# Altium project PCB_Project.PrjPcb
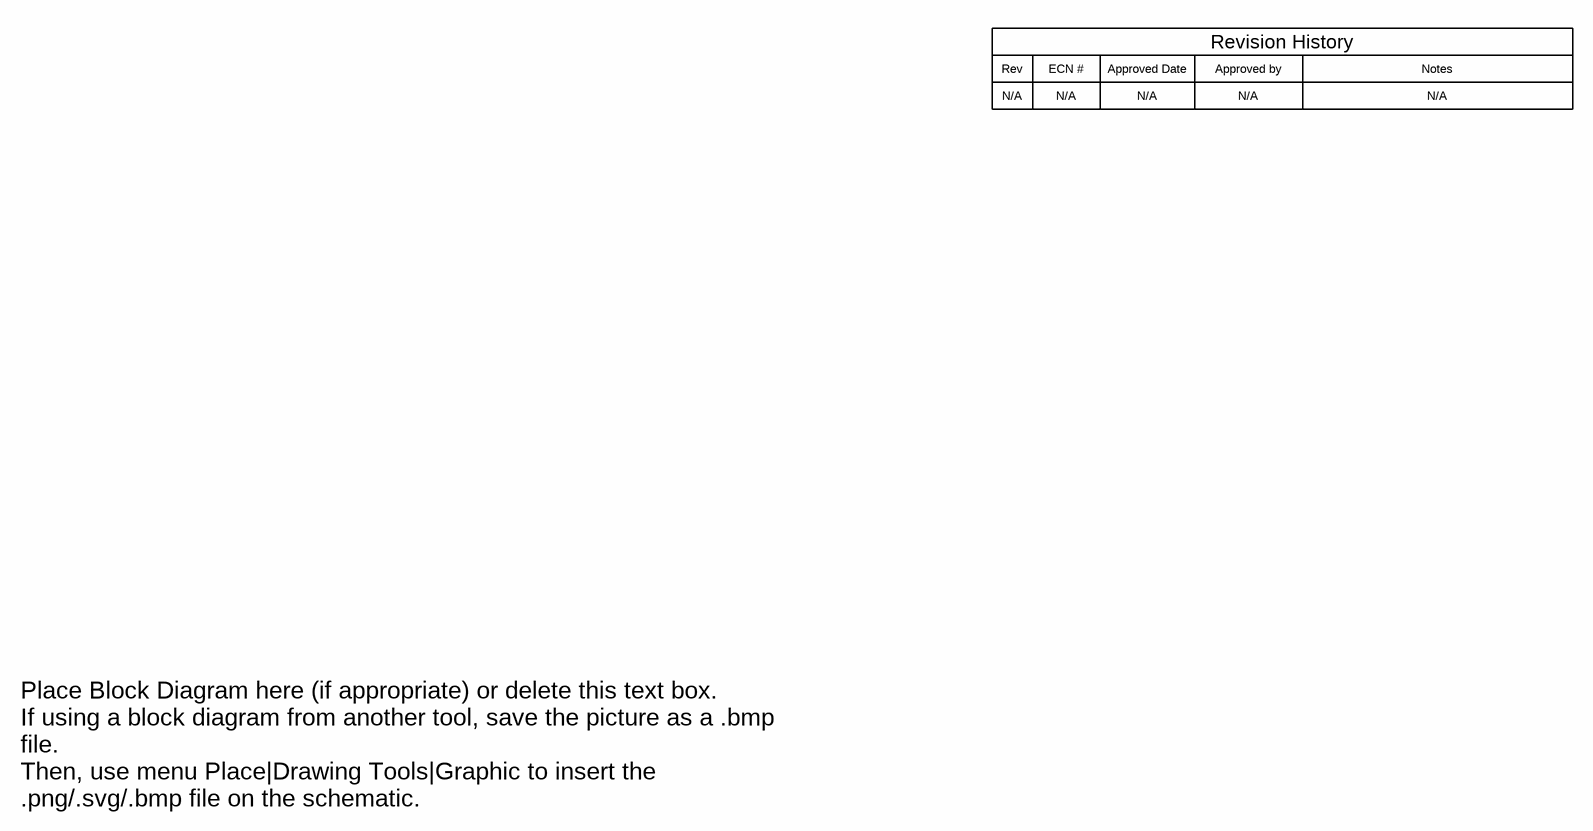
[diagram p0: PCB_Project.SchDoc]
TID: N/A; TechSupport: http://www.ti.com/support; SCH_Rev: E1; PRJ_Title: One Phage E-meteing with M0C; PRJ_Number: N/A; PRJ_Engineer: Joe Wang; PRJ_Customer: Public Release; PCB_Rev: E1; PCB_Layout: Joe Wang; CopyrightYear: 2025
3 sheets, 67 parts. Net scope: global (net labels, ports and power ports of the same name join across sheets).
Board file: PCB_Project.PcbDoc
Sheets:
  PCB_Project.SchDoc
  PCB_Project_BlankSheet.SchDoc
  PCB_Project_Hardware.SchDoc

## Sheet PCB_Project.SchDoc
size 431 x 279 mm; Date: Not shown in title block; ApprovedBy: Not shown in title block; CheckedBy: Not shown in title block; Author: Not shown in title block; CompanyName: Not shown in title block; Engineer: Not shown in title block; Organization: Not shown in title block; Address1: Not shown in title block; Address2: Not shown in title block; Address3: Not shown in title block; Address4: Not shown in title block; DocumentNumber: 1; Revision: Use project parameter SCH_Rev; SheetNumber: 1; SheetTotal: 3; PageSetup: Record=PageOptions¦CenterHorizontal=True¦CenterVertical=True¦PrintScale=1.00¦XCorrection=1.00¦YCorrection=1.00¦PrintKind=0¦BorderSize=5000000¦LeftOffset=0¦BottomOffset=0¦Orientation=2¦PaperLength=1000¦PaperWidth=1000¦Scale=100¦PaperSource=15¦PrintQuality=600¦MediaType=1¦DitherType=10¦PaperKind=Letter¦PrintScaleMode=1

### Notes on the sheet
- Rev
- N/A
- ECN #
- Approved Date
- Approved by
- Revision History
- Notes
- Place Block Diagram here (if appropriate) or delete this text box.
  If using a block diagram from another tool, save the picture as a .bmp file.
  Then, use menu Place|Drawing Tools|Graphic to insert the .png/.svg/.bmp file on the schematic.

## Sheet PCB_Project_BlankSheet.SchDoc
size 431 x 279 mm; Date: Not shown in title block; ApprovedBy: Not shown in title block; CheckedBy: Not shown in title block; Author: Not shown in title block; CompanyName: Not shown in title block; Engineer: Not shown in title block; Organization: Not shown in title block; Address1: Not shown in title block; Address2: Not shown in title block; Address3: Not shown in title block; Address4: Not shown in title block; DocumentNumber: 2; Revision: Use project parameter SCH_Rev; SheetNumber: 2; SheetTotal: 3; PageSetup: Record=PageOptions¦CenterHorizontal=True¦CenterVertical=True¦PrintScale=1.00¦XCorrection=1.00¦YCorrection=1.00¦PrintKind=0¦BorderSize=5000000¦LeftOffset=0¦BottomOffset=0¦Orientation=2¦PaperLength=1000¦PaperWidth=1000¦Scale=100¦PaperSource=15¦PrintQuality=600¦MediaType=1¦DitherType=10¦PaperKind=Letter¦PrintScaleMode=1
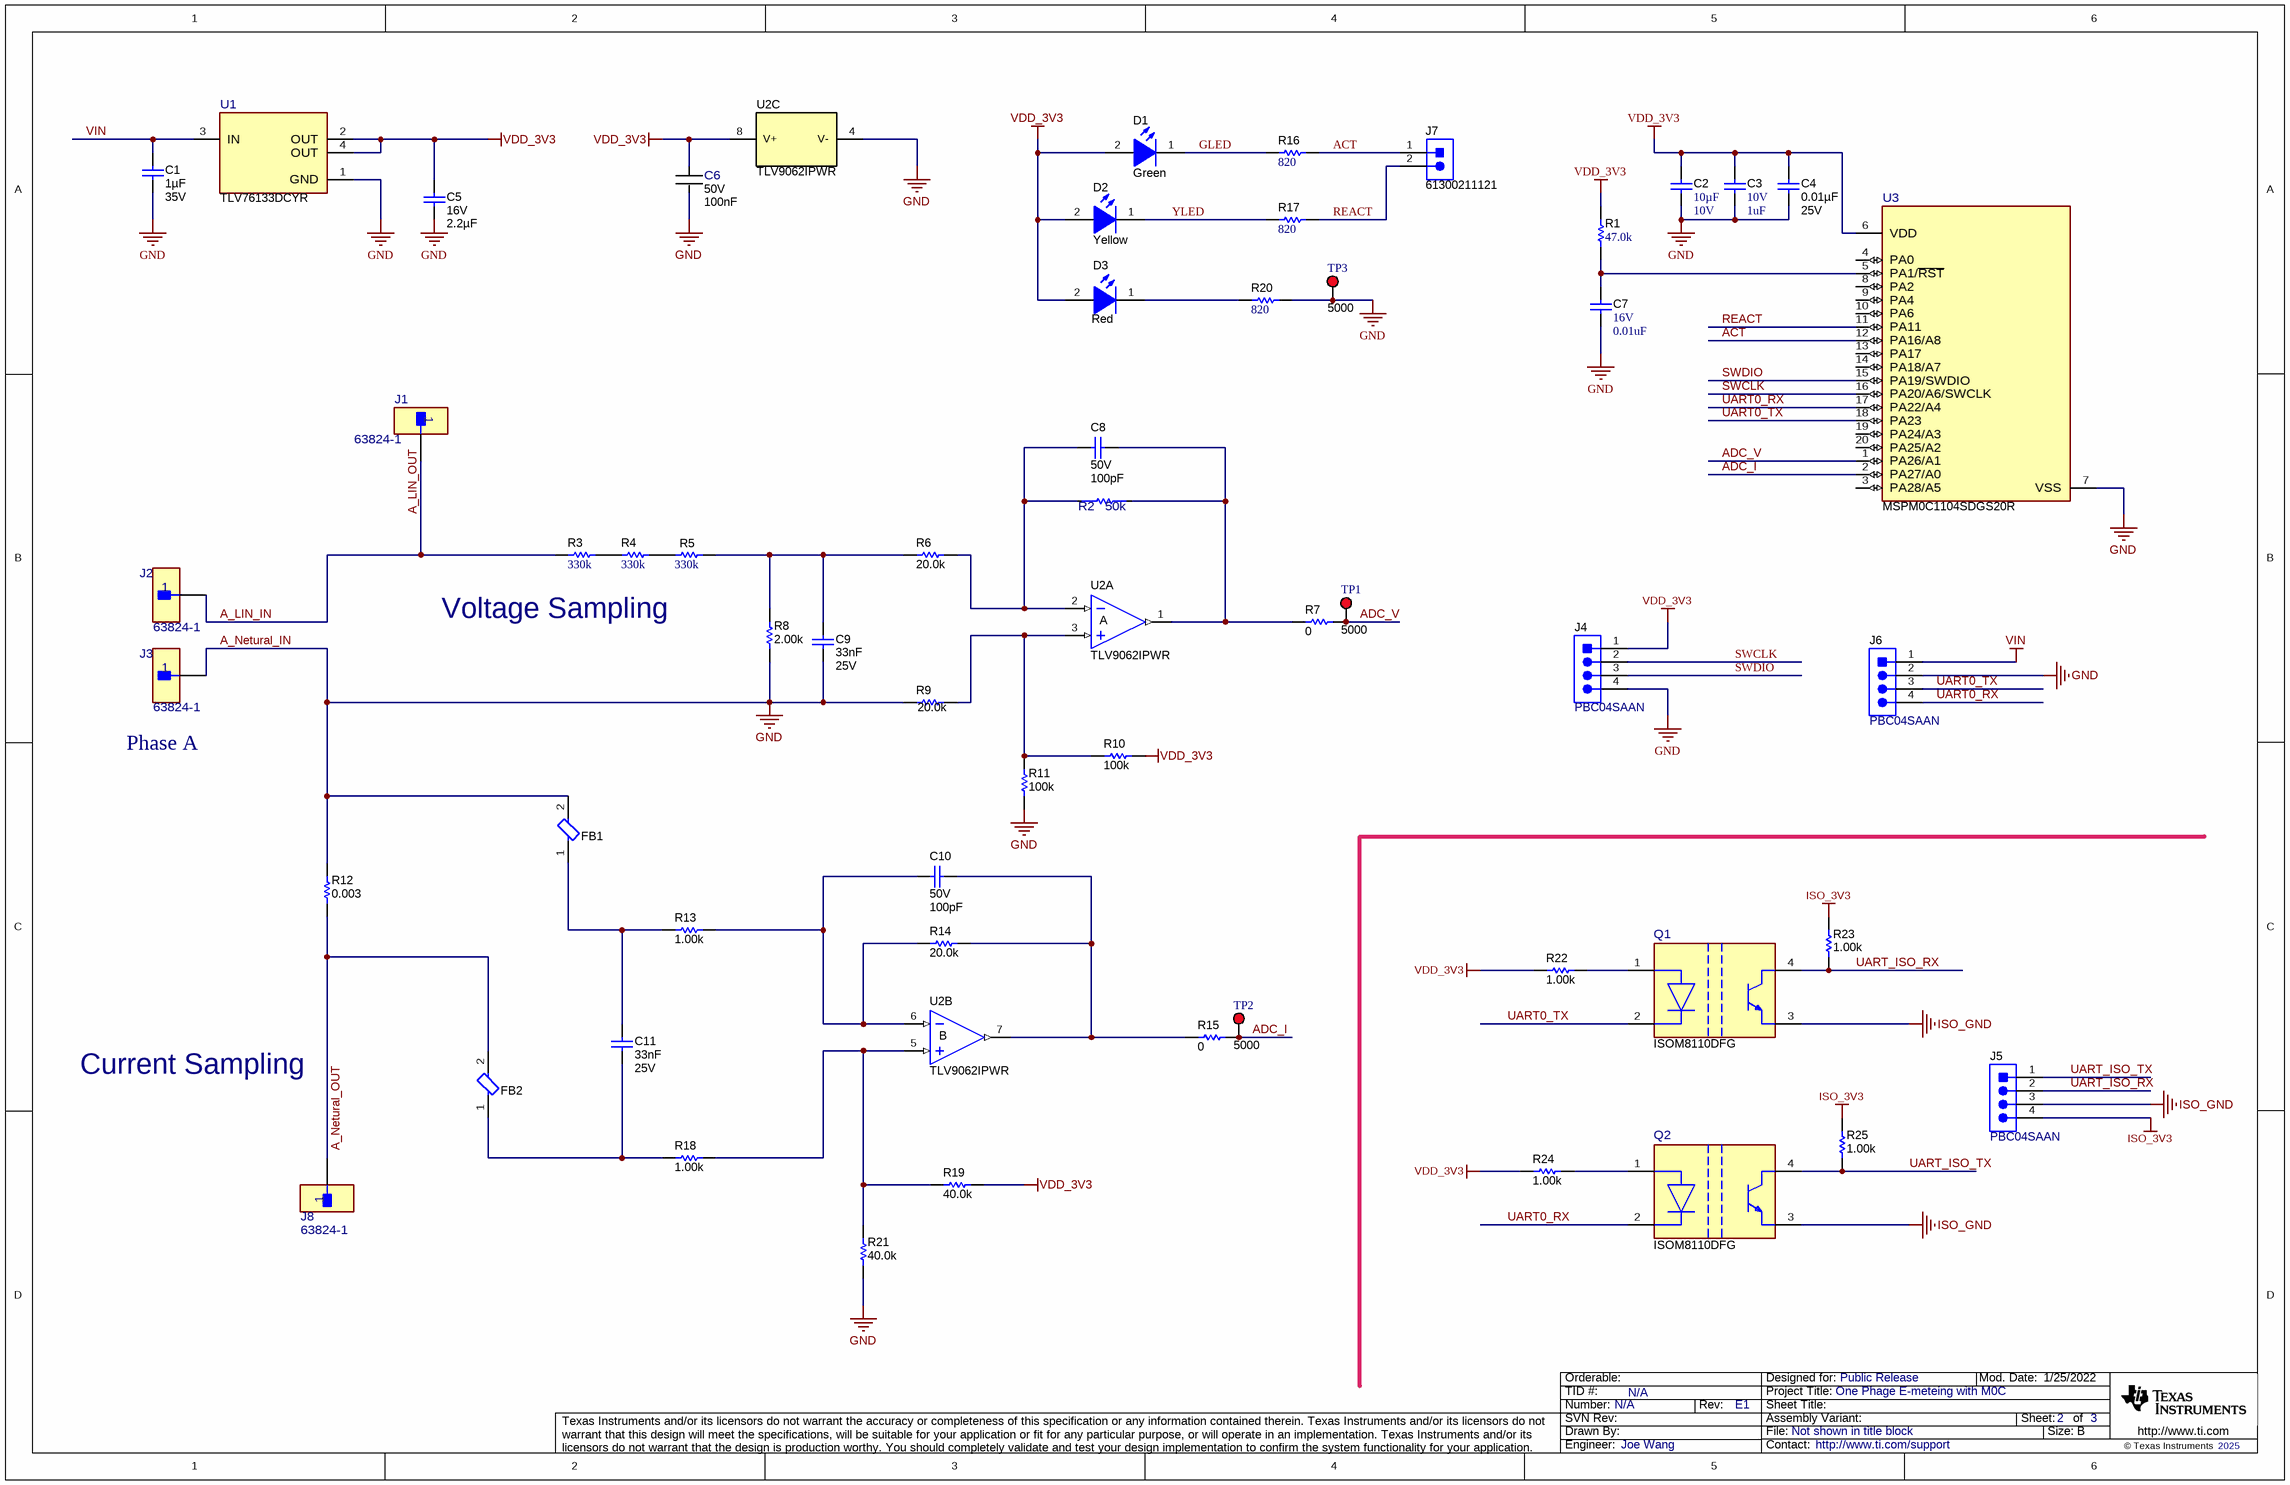
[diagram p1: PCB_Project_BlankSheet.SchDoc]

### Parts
C1  Cap_F: 1µF  VDC_V: 35V  [0603]  (hidden comment: CGA3E1X7R1V105K080AE)
C2  ValueDisplayed: 10µF  VDC_V: 10V  [0603]  (hidden comment: GRM188R61A106KAALD)
C3  VDC_V: 10V  ValueDisplayed: 1uF  [0402]  (hidden comment: GRM155C81A105KA12D)
C4  ValueDisplayed: 0.01µF  VDC_V: 25V  [0402]  (hidden comment: 04023C103JAT2A)
C5  VDC_V: 16V  Cap_F: 2.2µF  [0603]  (hidden comment: GRM188Z71C225KE43)
C6  VDC_V: 50V  Cap_F: 100nF  [FP-CL10B104KB8NNNC_0603-IPC_B]  (hidden comment: CL10B104KB8NNNC)
C7  VDC_V: 16V  ValueDisplayed: 0.01uF  [0402]  (hidden comment: C1005X7R1C103K050BA)
C8  VDC_V: 50V  ValueDisplayed: 100pF  [0603]  (hidden comment: C0603C101F5GACTU)
C9  Cap_F: 33nF  VDC_V: 25V  [0603]  (hidden comment: C0603C333J3RACTU)
C10  VDC_V: 50V  ValueDisplayed: 100pF  [0603]  (hidden comment: C0603C101F5GACTU)
C11  Cap_F: 33nF  VDC_V: 25V  [0603]  (hidden comment: C0603C333J3RACTU)
D1  value Green  [WL-SMCW_GREEN]  (hidden comment: 150060VS75000)
D2  value Yellow  [WL-SMCW_YELLOW]  (hidden comment: 150060YS75000)
D3  value Red  [WL-SMCW_RED]  (hidden comment: 150060RS75000)
FB1  74269244182  [FP-74269244182_0402-MFG]  (value not drawn)
FB2  74269244182  [FP-74269244182_0402-MFG]  (value not drawn)
J1  63824-1  [FP-63824-1_CONN_7MM92_3MM11-MFG]
J2  63824-1  [FP-63824-1_CONN_7MM92_3MM11-MFG]
J3  63824-1  [FP-63824-1_CONN_7MM92_3MM11-MFG]
J4  PBC04SAAN  [Sullins_xxC04SAAN]
J5  PBC04SAAN  [Sullins_xxC04SAAN]
J6  PBC04SAAN  [Sullins_xxC04SAAN]
J7  61300211121  [WURTH_61300211121]
J8  63824-1  [FP-63824-1_CONN_7MM92_3MM11-MFG]
Q1  ISOM8110DFG  [DFG0004A-MFG]
Q2  ISOM8110DFG  [DFG0004A-MFG]
R1  ValueDisplayed: 47.0k  [0402]  (hidden comment: RC0402FR-0747KL)
R2  50k  [FP-RT0603BRD0750KL_0603-MFG]
R3  ValueDisplayed: 330k  [TNPV1206]  (hidden comment: TNPV1206330KBEEN)
R4  ValueDisplayed: 330k  [TNPV1206]  (hidden comment: TNPV1206330KBEEN)
R5  ValueDisplayed: 330k  [TNPV1206]  (hidden comment: TNPV1206330KBEEN)
R6  ValueDisplayed: 20.0k  [0603]  (hidden comment: RT0603BRD0720KL)
R7  ValueDisplayed: 0  [0603]  (hidden comment: ERJ-3GEY0R00V)
R8  ValueDisplayed: 2.00k  [0603]  (hidden comment: RT0603BRD072KL)
R9  ValueDisplayed: 20.0k  [0603]  (hidden comment: RT0603BRD0720KL)
R10  ValueDisplayed: 100k  [0603]  (hidden comment: RG1608P-104-B-T5)
R11  ValueDisplayed: 100k  [0603]  (hidden comment: RG1608P-104-B-T5)
R12  ValueDisplayed: 0.003  [CRE2512-R1_R4]  (hidden comment: CRE2512-FZ-R003E-3)
R13  ValueDisplayed: 1.00k  [0603]  (hidden comment: RT0603DRE071KL)
R14  ValueDisplayed: 20.0k  [0603]  (hidden comment: RT0603BRD0720KL)
R15  ValueDisplayed: 0  [0603]  (hidden comment: ERJ-3GEY0R00V)
R16  value 820  [0402]  (hidden comment: RC0402FR-07820RL)
R17  value 820  [0402]  (hidden comment: RC0402FR-07820RL)
R18  ValueDisplayed: 1.00k  [0603]  (hidden comment: RT0603DRE071KL)
R19  ValueDisplayed: 40.0k  [0603]  (hidden comment: PAT0603E4002BST1)
R20  value 820  [0402]  (hidden comment: RC0402FR-07820RL)
R21  ValueDisplayed: 40.0k  [0603]  (hidden comment: PAT0603E4002BST1)
R22  ValueDisplayed: 1.00k  [0603]  (hidden comment: RT0603DRE071KL)
R23  ValueDisplayed: 1.00k  [0603]  (hidden comment: RT0603DRE071KL)
R24  ValueDisplayed: 1.00k  [0603]  (hidden comment: RT0603DRE071KL)
R25  ValueDisplayed: 1.00k  [0603]  (hidden comment: RT0603DRE071KL)
TP1  5000  [Keystone5000]
TP2  5000  [Keystone5000]
TP3  5000  [Keystone5000]
U1  TLV76133DCYR  [DCY0004A-MFG]
U2  TLV9062IPWR  [PW0008A_N]  (parts A,B,C of 3)
U3  MSPM0C1104SDGS20R  [DGS0020A-MFG]

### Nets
A_Netural_IN: C1.2 C2.2 C3.2 C4.1 C5.2 C6.2 C7.2 C9.2 FB1.2 J3.1 J4.4 J6.2 R8.1 R9.1 R11.1 R12.2 R20.1 R21.1 TP3.1 U1.1(GND) U2.4(V-) U3.7(VSS)  [also labelled GND]
ISO_3V3: J5.4 R23.2 R25.2
ISO_GND: J5.3 Q1.3(Emitter) Q2.3(Emitter)
VDD_3V3: C2.1 C3.1 C4.2 C5.1 C6.1 D1.2(A) D2.2(A) D3.2(A) J4.1 R1.2 R10.2 R19.1 R22.1 R24.1 U1.2(OUT) U1.4(OUT) U2.8(V+) U3.6(VDD)
VIN: C1.1 J6.1 U1.3(IN)
A_LIN_IN: J1.1 J2.1 R3.2  [also labelled A_LIN_OUT]
A_Netural_OUT: FB2.2 J8.1 R12.1
ACT: J7.1 R16.1 U3.12(PA16/A8)
ADC_I: R15.2 TP2.1 U3.2(PA27/A0)
ADC_V: R7.2 TP1.1 U3.1(PA26/A1)
GLED: D1.1(K) R16.2
REACT: J7.2 R17.1 U3.11(PA11)
SWCLK: J4.2 U3.16(PA20/A6/SWCLK)
SWDIO: J4.3 U3.15(PA19/SWDIO)
UART0_RX: J6.4 Q2.2(CAT) U3.17(PA22/A4)
UART0_TX: J6.3 Q1.2(CAT) U3.18(PA23)
UART_ISO_RX: J5.2 Q1.4(Collector) R23.1
UART_ISO_TX: J5.1 Q2.4(Collector) R25.1
YLED: D2.1(K) R17.2
NetC7_1: C7.1 R1.1 U3.5(PA1/~{RST})
NetC8_1: C8.1 R2.2 R7.1 U2.1(OUT)
NetC8_2: C8.2 R2.1 R6.2 U2.2(IN-)
NetC9_1: C9.1 R5.2 R6.1 R8.2
NetC10_1: C10.1 R14.2 R15.1 U2.7(OUT)
NetC10_2: C10.2 R13.2 R14.1 U2.6(IN-)
NetC11_1: C11.1 FB1.1 R13.1
NetC11_2: C11.2 FB2.1 R18.1
NetD3_1: D3.1(K) R20.2
NetQ1_1: Q1.1(AN) R22.2
NetQ2_1: Q2.1(AN) R24.2
NetR3_1: R3.1 R4.2
NetR4_1: R4.1 R5.1
NetR9_2: R9.2 R10.1 R11.2 U2.3(IN+)
NetR18_2: R18.2 R19.2 R21.2 U2.5(IN+)

Not connected (* = marked no-connect by the designer): U3 3(PA28/A5) 4(PA0) 8(PA2) 9(PA4) 10(PA6) 13(PA17) 14(PA18/A7) 19(PA24/A3) 20(PA25/A2)

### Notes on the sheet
- Voltage Sampling
- Phase A
- Current Sampling

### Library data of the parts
C1 = CMP-0081259-1: CAP, CERM, 1 µF, 35 V,+/- 10%, X7R, AEC-Q200 Grade 1, 0603; Manufacturer: TDK; SizeAreaWB_mm2: 4.68; SizeArea_mm2: 1.28; AEC Qualified: Y; AEC Category: Q200; Value: 1uF; TaMax_C: 125°C; SizeZ_mm: 1; Polarized: N; TaMin_C: -55°C; SizeY_mm: 0.8; U/M: EA; SizeX_mm: 1.6
C2 = CMP-0086193-1: CAP, CERM, 10 µF, 10 V,+/- 10%, X5R, 0603; Manufacturer: MuRata; SizeArea_mm2: 1.28; SizeY_mm: 0.8; TaMax_C: 85°C; TaMin_C: -55°C; Polarized: N; SizeAreaWB_mm2: 4.68; SizeZ_mm: 1; SizeX_mm: 1.6; AEC Category: Q200; U/M: EA; Value: 10uF
C3 = CMP-0064971-2: CAP, CERM, 1 uF, 10 V,+/- 10%, X6S, 0402; Manufacturer: MuRata; TaMin_C: -55°C; Polarized: N; SizeAreaWB_mm2: 3; Value1: Unknown; U/M: EA; Value: 1uF; TaMax_C: 105°C; SizeZ_mm: 0.6; SizeX_mm: 1; SizeY_mm: 0.5; Cap_F: 1µF; AEC Category: Q200
C4 = CMP-0085568-1: CAP, CERM, 0.01 µF, 25 V,+/- 5%, X7R, 0402; Manufacturer: AVX; AEC Category: Q200; SizeAreaWB_mm2: 3; SizeArea_mm2: 0.5; Polarized: N; TaMin_C: -55°C; Value: 0.01uF; U/M: EA; SizeX_mm: 1; Cap_F: 10nF; SizeZ_mm: 0.6; TaMax_C: 125°C
C5 = CMP-0007499-1: CAP, CERM, 2.2 uF, 16 V, +/- 10%, X7R, 0603; Manufacturer: MuRata; TaMin_C: -55°C; Polarized: N; SizeAreaWB_mm2: 4.68; Value1: Unknown; U/M: EA; Value: 2.2uF; TaMax_C: 125°C; SizeZ_mm: 1; SizeX_mm: 1.6; SizeY_mm: 0.8; SizeArea_mm2: 1.28; AEC Category: Q200
C6 = CMP-0087079-1: CAP CER 0.1UF 50V X7R 0603; Manufacturer: Samsung; Tolerance_%: 10%; Symbol Name: SYM-CL10B104KB8NNNC; AEC Qualified: No; TempCo: 15%; SizeZ_mm: 0.9mm
C7 = CMP-0006292-2: CAP, CERM, 0.01 uF, 16 V, +/- 10%, X7R, 0402; Manufacturer: TDK; TaMin_C: -55°C; Polarized: N; SizeAreaWB_mm2: 3; Value1: 0.0623 ohm; U/M: EA; Value: 0.01uF; TaMax_C: 125°C; SizeZ_mm: 0.6; SizeX_mm: 1; SizeY_mm: 0.5; Cap_F: 10nF; AEC Category: Q200; ESR_ohm: 62.3m
C8 C10 = CMP-0080091-1: CAP, CERM, 100 pF, 50 V,+/- 1%, C0G/NP0, 0603; Manufacturer: Kemet; SizeAreaWB_mm2: 4.68; SizeArea_mm2: 1.28; AEC Qualified: N; AEC Category: Q200; Value: 100pF; TaMax_C: 125°C; SizeZ_mm: 1; Green_REACh: Passed; TaMin_C: -55°C; SizeY_mm: 0.8; Green_Lifecycle: Active; U/M: EA; SizeX_mm: 1.6
C9 C11 = CMP-0006923-4: CAP, CERM, 0.033 uF, 25 V, +/- 5%, X7R, 0603; Manufacturer: Kemet; TaMin_C: -55°C; Polarized: N; SizeAreaWB_mm2: 4.68; Value1: Unknown; U/M: EA; TaMax_C: 125°C; SizeZ_mm: 1; SizeX_mm: 1.6; SizeY_mm: 0.8; SizeArea_mm2: 1.28; AEC Category: Q200
D1 = CMP-0002894-2: LED, Green, SMD; Manufacturer: Wurth Elektronik; Type: AlInGaP; Vf_V: 2V; Io_A: 20mA; Value1: W
D2 = CMP-0002892-3: LED, Yellow, SMD; Manufacturer: Wurth Elektronik; Type: AlInGaP; Vf_V: 2V; Io_A: 20mA; Value1: W
D3 = CMP-0002947-2: LED, Red, SMD; Manufacturer: Wurth Elektronik; Io_A: 30mA; Power_TotalModule: 72mW; Vr_V: 5V; Tjmax_C: 85°C; Value1: 0.072W; U/M: EA; Angle: 140; Vf_V: 2V; Type: AlInGaP
FB1 FB2 = CMP-0091663-1: 1.8 kOhms @ 100MHz 1 Power, Signal Line Ferrite Bead 0402 (1005 Metric) 210mA 2.1Ohm; Manufacturer: Wurth Electronics; SizeZ_mm: 0.55mm; AEC Qualified: No; DCR_ohm: 2.1; Tolerance_%: 25%; Test Frequency: 1GHz; Impedance At Frequency: 1800Ω @ 100MHz
J1-J3 J8 = CMP-0089624-1: Manufacturer: TE Connectivity; SizeZ_mm: 10.71mm; Conn Gender: Male; Conn Orientation: Straight; AEC Qualified: No; Import Ts: 1521847382; ContactFinish: Tin,Nickel; Current_A: 20A; Ciiva Ids: 766930
J4-J6 = CMP-0054583-1: Header, 2.54 mm, 4x1, Gold, TH; Manufacturer: Sullins Connector Solutions; CNHeader: TRUE; Current_A: 3A; Green_Lifecycle: Not Set; Shrouded: N; Gender: Male; Green_REACh: Incomplete; Voltage_V: 1.8kV; Row_Count: 1; Pitch_mm: 2.54; CT: FALSE; Cert_UL: Y
J7 = CMP-0054794-2: Header, 2.54 mm, 2x1, Gold, TH; Manufacturer: Wurth Elektronik; Green_Lifecycle: Active; Shrouded: N; Gender: Male; Green_REACh: Passed; Row_Count: 1; Pitch_mm: 2.54; Cert_UL: Y
Q1 Q2 = CMP-0098363-1: 3.75-kVRMS, Single-Channel Opto-Emulator with Transistor Output; Manufacturer: Texas Instruments; SizeZ_mm: 2.65mm; AEC Qualified: No; CTR (Max): 160%; CTR (Min): 80%; Emiiter Collector Voltage: 7V; Forward Current: 10mA; Power_TotalModule: 200mW; Standoff Height: 0.05mm; TaMax_C: +125°C; TaMin_C: -55°C; TJmax_C: +150°C; Turn Off Delay Time: 5us; Turn On Delay Time: 1.7us; Value: 80V; Vf_V: 1.1V; Voltage_Isolation_Vrms: 3750Vrms
R1 = CMP-0026737-1: RES, 47.0 k, 1%, 0.0625 W, 0402; Manufacturer: Yageo America; Power_W: 62.5mW; TempCo: 100 ppm/C; Value_Code: 47k0; Value: 47.0k; Res_ohm: 47k; SizeX_mm: 1; SizeY_mm: 0.5; SizeZ_mm: 0.6; AEC Qualified: N; VDC_V: 50V; AEC Category: Q200; U/M: EA
R2 = CMP-0096502-1: High Precision-High Stability Chip Resistor Thin Film 0603 50kOhm 0.1% Paper T/R; Part Number: RT0603BRD0750KL; Manufacturer: Yageo; SizeZ_mm: 0.55mm; VDC_V: 75V; TempCo: 25ppm/°C; Power_W: 100mW; AEC Qualified: No
R3-R5 = CMP-0018811-2: RES, 330 k, 0.1%, 1 W, 1206; Manufacturer: Vishay Draloric; Power_W: 1W; TempCo: 25 ppm/C; U/M: EA; Value: 330k; SizeX_mm: 3.2; SizeY_mm: 1.6; SizeZ_mm: 0.65; SizeArea_mm2: 5.12; AEC Qualified: N; VDC_V: 700V; AEC Category: Q200
R6 R9 R14 = CMP-0023931-3: RES, 20.0 k, 0.1%, 0.1 W, 0603; Manufacturer: Yageo America; Power_W: 100mW; TempCo: 25 ppm/C; Value_Code: 20k0; U/M: EA; Value: 20.0k; EIA_Code: E192; Res_ohm: 20k; SizeX_mm: 1.6; SizeZ_mm: 1; SizeY_mm: 0.8; Value2: 0.1W; SizeArea_mm2: 1.28; VDC_V: 75V; AEC Category: Q200
R7 R15 = CMP-0025874-2: RES, 0, 5%, 0.1 W, 0603; Manufacturer: Panasonic; Power_W: 100mW; TempCo: 600 ppm/C; Value_Code: 0000; U/M: EA; Value: 0; EIA_Code: E24; SizeX_mm: 1.6; SizeY_mm: 0.8; SizeZ_mm: 1; Value2: 0.1W; SizeArea_mm2: 1.28; VDC_V: 50V; AEC Category: Q200
R8 = CMP-0024089-2: RES, 2.00 k, 0.1%, 0.1 W, 0603; Manufacturer: Yageo America; Power_W: 100mW; TempCo: 25 ppm/C; Value_Code: 2k00; U/M: EA; Value: 2.00k; EIA_Code: E192; Res_ohm: 2k; SizeX_mm: 1.6; SizeY_mm: 0.8; SizeZ_mm: 1; Value2: 0.1W; SizeArea_mm2: 1.28; VDC_V: 75V; AEC Category: Q200
R10 R11 = CMP-0023405-1: RES, 100 k, 0.1%, 0.1 W, 0603; Manufacturer: Susumu Co Ltd; Power_W: 100mW; TempCo: 25 ppm/C; U/M: EA; Value: 100k; EIA_Code: E192; SizeX_mm: 1.6; SizeY_mm: 0.8; SizeZ_mm: 1; Value2: 0.1W; SizeArea_mm2: 1.28; VDC_V: 75V; AEC Category: Q200
R12 = CMP-0015750-2: RES, 0.003, 1%, 3 W, AEC-Q200 Grade 0, 2512; Manufacturer: Bourns; Power_W: 3W; TempCo: 50 ppm/C; Value_Code: 3L000; U/M: EA; Value: 0.003; EIA_Code: E96; Res_ohm: 3m; SizeX_mm: 6.45; SizeY_mm: 3.35; SizeZ_mm: 0.9; SizeArea_mm2: 21.6075; AEC Qualified: Y; AEC Grade: 0; AEC Category: Q200
R13 R18 R22-R25 = CMP-0024852-1: RES, 1.00 k, 0.5%, 0.1 W, 0603; Manufacturer: Yageo America; Power_W: 100mW; TempCo: 50 ppm/C; Value_Code: 1k00; U/M: EA; Value: 1.00k; EIA_Code: E192; Res_ohm: 1k; SizeX_mm: 1.6; SizeY_mm: 0.8; SizeZ_mm: 1; Value2: 0.1W; SizeArea_mm2: 1.28; VDC_V: 75V; AEC Category: Q200
R16 R17 R20 = CMP-0026743-1: RES, 820, 1%, 0.063 W, 0402; Manufacturer: Yageo America; Value_Code: 820R; Power_W: 63mW; Value2: 0.063W; VDC_V: 50V; TempCo: 100 ppm/C; U/M: EA; AEC Category: Q200; AEC Qualified: N; SizeArea_mm2: 0.5; SizeX_mm: 1; SizeZ_mm: 0.6
R19 R21 = CMP-0860025-1: RES, 40.0 k, 0.1%, 0.15 W, AEC-Q200 Grade 0, 0603; Manufacturer: Vishay Thin Film; SizeArea_mm2: 1.28; AEC Grade: 0; SizeAreaWB_mm2: 4.68; Value: 40.0k; Value_Code: 40k0; SizeZ_mm: 1; AEC Qualified: Y; AEC Category: Q200; Power_W: 150mW; SizeY_mm: 0.8; SizeX_mm: 1.6; TempCo: 25 ppm/C; Value2: 0.15W; Res_ohm: 40k
TP1-TP3 = CMP-0055137-2: Test Point, Miniature, Red, TH; Manufacturer: Keystone Electronics; Green_REACh: Passed; Green_Lifecycle: Active; ContactFinish: Silver; CNHeader: FALSE; CT: TRUE
U1 = CMP-0122558-1: 1-A 16-V high-PSRR linear voltage regulator 4-SOT-223 -40 to 125; Manufacturer: Texas Instruments; SizeZ_mm: 1.8mm; AEC Qualified: No; Accuracy Percentage: 1%; Dropout Voltage: 0.9V; Max Supply Voltage: 16V; Min Supply Voltage: 4.8V; Nominal Supply Current: 65uA; Number Of Outputs: 1; Output Type: Fixed; Output Voltage: 3.3V; Standoff Height: 0.02mm; TJmax_C: +125°C
U2 = CMP-0084065-1: 10-MHz, Low-Noise, RRIO, CMOS Operational Amplifier for Cost-Sensitive Systems, PW0008A (TSSOP-8); Manufacturer: Texas Instruments; Rating: Catalog; SizeAreaWB_mm2: 42; SizeArea_mm2: 19.2; AEC Qualified: N; AEC Category: Q200; SizeZ_mm: 1.2; SizeY_mm: 3; CompType: IC; SizeX_mm: 6.4
U3 = CMP-0121923-1: Mixed-Signal Microcontrollers; Manufacturer: Texas Instruments; SizeZ_mm: 1.1mm; AEC Qualified: No; Core Architecture: ARM Cortex-M0+; Data Bus Width: 32bits; Frequency_Fixed: 24MHz; Interface: I2C,SPI,UART,LIN,IrDA,SMBus,Other; Max Supply Voltage: 3.6V; Memory Size: 16KBytes; Memory Type: FLASH; Min Supply Voltage: 1.62V; Number Of A/D Converters: 1; Number Of Adc Channels: 10; Number Of I/Os: 18; Number Of Pwm Channels: 14; Number Of Timers/Counters: 3; Ram Size: 1KBytes; Standoff Height: 0.05mm; TaMax_C: +125°C; TaMin_C: -40°C; TJmax_C: +130°C

## Sheet PCB_Project_Hardware.SchDoc
size 431 x 279 mm; Date: Not shown in title block; ApprovedBy: Not shown in title block; CheckedBy: Not shown in title block; Author: Not shown in title block; CompanyName: Not shown in title block; Engineer: Not shown in title block; Organization: Not shown in title block; Address1: Not shown in title block; Address2: Not shown in title block; Address3: Not shown in title block; Address4: Not shown in title block; DocumentNumber: 3; Revision: Use project parameter SCH_Rev; SheetNumber: 3; SheetTotal: 3; PageSetup: Record=PageOptions¦CenterHorizontal=True¦CenterVertical=True¦PrintScale=1.00¦XCorrection=1.00¦YCorrection=1.00¦PrintKind=0¦BorderSize=5000000¦LeftOffset=0¦BottomOffset=0¦Orientation=2¦PaperLength=1000¦PaperWidth=1000¦Scale=100¦PaperSource=15¦PrintQuality=600¦MediaType=1¦DitherType=10¦PaperKind=Letter¦PrintScaleMode=1
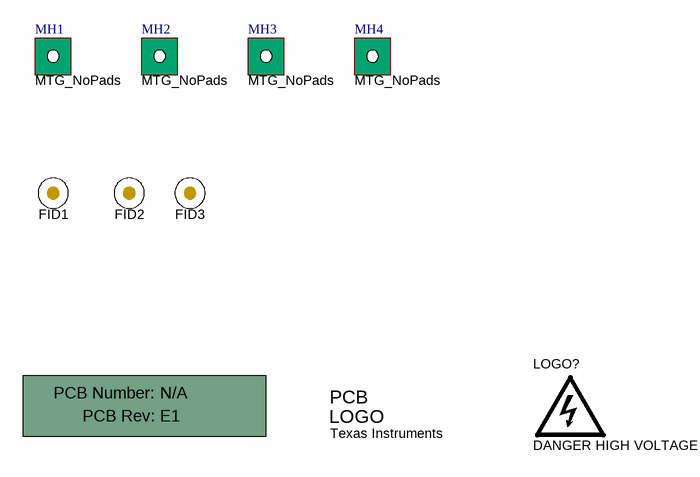
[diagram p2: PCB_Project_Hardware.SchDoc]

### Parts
!PCB  Printed Circuit Board  (value not drawn)  (mechanical)
FID1  Fiducial  [Fiducial10-20]  (value not drawn)
FID2  Fiducial  [Fiducial10-20]  (value not drawn)
FID3  Fiducial  [Fiducial10-20]  (value not drawn)
Logo1  Texas Instruments  [TI_Stacked_Overlay_Small]  (no BOM)
LOGO?  DANGER HIGH VOLTAGE  [IEC_HighVoltage_Small]  (no BOM)
MH1  MTG_NoPads  [NPTH125mil]  (no BOM)
MH2  MTG_NoPads  [NPTH125mil]  (no BOM)
MH3  MTG_NoPads  [NPTH125mil]  (no BOM)
MH4  MTG_NoPads  [NPTH125mil]  (no BOM)

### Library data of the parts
!PCB = CMP-0003618-2: Manufacturer: Any
FID1-FID3 = CMP-0077181-1: Fiducial mark.  There is nothing to buy or mount.
Logo1 = CMP-0074838-1: Texas Instrument Corporate Signature; SymbolCreator: a0412235; Lib Reference: TI_Logo; Library Reference: Logo
LOGO? = CMP-0074835-1: IEC 61010-1 High Voltage Warning; SymbolCreator: a0412235
MH1-MH4 = CMP-0078424-2: PCB Mounting Hole, No Pad; Manufacturer: Any; Key: Mounting Hole (non-standard) No Pad

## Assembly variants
001: not fitted FID1 FID2 FID3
